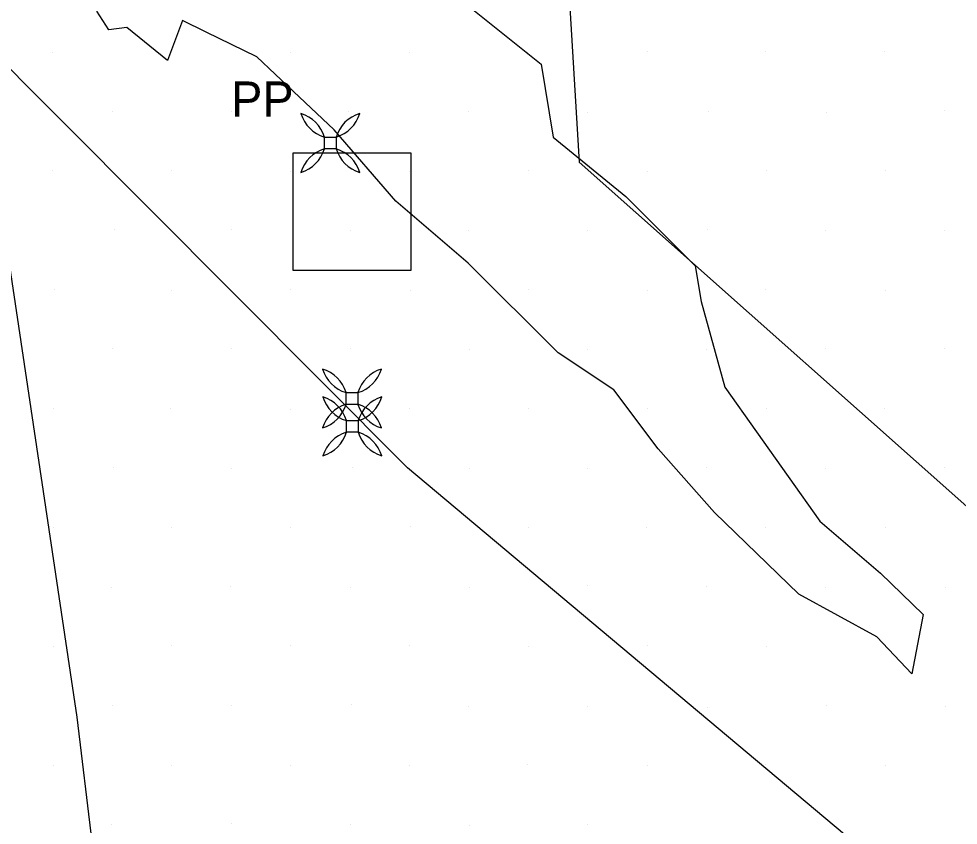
# Model space of a CAD drawing. Extents: x 1602514 to 1609837, y 863887 to 871157.
# Drawn here: x 1605707.9 to 1605875.4, y 865775.6 to 865919.5 of the extents above; entities that cross this region are included whole.
import ezdxf

# ---------------------------------------------------------------- set-up
doc = ezdxf.new("R2010")
doc.units = 0
for name, color, linetype in [('Photo-Anchor', 7, 'Continuous'), ('Survey-Entrances', 7, 'Continuous'), ('Survey-Spot dirt', 7, 'Continuous'), ('Survey-Vegetation trees', 7, 'Continuous'), ('Utility-Pole', 7, 'Continuous')]:
    doc.layers.add(name, color=color, linetype=linetype)

msp = doc.modelspace()

# ---------------------------------------------------------------- linework, layer by layer
at = {"layer": 'Photo-Anchor'}
for points in [[(1605762.4, 865898.37), (1605764.5, 865898.37), (1605764.5, 865896.27), (1605762.4, 865896.27)], [(1605762.4, 865898.37), (1605764.5, 865898.37), (1605764.5, 865896.27), (1605762.4, 865896.27)], [(1605766.26, 865852.78), (1605768.36, 865852.78), (1605768.36, 865850.68), (1605766.26, 865850.68)], [(1605766.26, 865852.78), (1605768.36, 865852.78), (1605768.36, 865850.68), (1605766.26, 865850.68)], [(1605766.33, 865847.8), (1605768.43, 865847.8), (1605768.43, 865845.7), (1605766.33, 865845.7)], [(1605766.33, 865847.8), (1605768.43, 865847.8), (1605768.43, 865845.7), (1605766.33, 865845.7)]]:
    msp.add_lwpolyline(points, close=True, dxfattribs=at)
for centre, radius, start, end in [((1605756.4, 865896.57), 6.27, 16.7236, 73.2821), ((1605764.22, 865904.39), 6.29, 196.8106, 253.1951), ((1605756.4, 865896.57), 6.27, 16.7236, 73.2821), ((1605764.22, 865904.39), 6.29, 196.8106, 253.1951), ((1605770.5, 865896.57), 6.27, 106.7179, 163.2764), ((1605762.68, 865904.39), 6.29, 286.8049, 343.1894), ((1605770.5, 865896.57), 6.27, 106.7179, 163.2764), ((1605762.68, 865904.39), 6.29, 286.8049, 343.1894), ((1605756.4, 865898.08), 6.27, 286.7179, 343.2764), ((1605764.22, 865890.25), 6.29, 106.8049, 163.1894), ((1605756.4, 865898.08), 6.27, 286.7179, 343.2764), ((1605764.22, 865890.25), 6.29, 106.8049, 163.1894), ((1605770.5, 865898.08), 6.27, 196.7236, 253.2821), ((1605762.68, 865890.25), 6.29, 16.8106, 73.1951), ((1605770.5, 865898.08), 6.27, 196.7236, 253.2821), ((1605762.68, 865890.25), 6.29, 16.8106, 73.1951), ((1605760.26, 865850.98), 6.27, 16.7236, 73.2821), ((1605768.08, 865858.8), 6.29, 196.8106, 253.1951), ((1605760.26, 865850.98), 6.27, 16.7236, 73.2821), ((1605768.08, 865858.8), 6.29, 196.8106, 253.1951), ((1605774.37, 865850.98), 6.27, 106.7179, 163.2764), ((1605766.55, 865858.8), 6.29, 286.8049, 343.1894), ((1605774.37, 865850.98), 6.27, 106.7179, 163.2764), ((1605766.55, 865858.8), 6.29, 286.8049, 343.1894), ((1605760.32, 865846), 6.27, 16.7236, 73.2821), ((1605768.14, 865853.82), 6.29, 196.8106, 253.1951), ((1605760.32, 865846), 6.27, 16.7236, 73.2821), ((1605768.14, 865853.82), 6.29, 196.8106, 253.1951), ((1605774.43, 865846), 6.27, 106.7179, 163.2764), ((1605766.61, 865853.82), 6.29, 286.8049, 343.1894), ((1605774.43, 865846), 6.27, 106.7179, 163.2764), ((1605766.61, 865853.82), 6.29, 286.8049, 343.1894), ((1605760.26, 865852.49), 6.27, 286.7179, 343.2764), ((1605768.08, 865844.67), 6.29, 106.8049, 163.1894), ((1605760.26, 865852.49), 6.27, 286.7179, 343.2764), ((1605768.08, 865844.67), 6.29, 106.8049, 163.1894), ((1605774.37, 865852.49), 6.27, 196.7236, 253.2821), ((1605766.55, 865844.67), 6.29, 16.8106, 73.1951), ((1605774.37, 865852.49), 6.27, 196.7236, 253.2821), ((1605766.55, 865844.67), 6.29, 16.8106, 73.1951), ((1605760.32, 865847.51), 6.27, 286.7179, 343.2764), ((1605768.14, 865839.68), 6.29, 106.8049, 163.1894), ((1605760.32, 865847.51), 6.27, 286.7179, 343.2764), ((1605768.14, 865839.68), 6.29, 106.8049, 163.1894), ((1605774.43, 865847.51), 6.27, 196.7236, 253.2821), ((1605766.61, 865839.68), 6.29, 16.8106, 73.1951), ((1605774.43, 865847.51), 6.27, 196.7236, 253.2821), ((1605766.61, 865839.68), 6.29, 16.8106, 73.1951)]:
    msp.add_arc(centre, radius, start, end, dxfattribs=at)
at = {"layer": 'Survey-Entrances'}
msp.add_lwpolyline([(1605786.77, 865922.81), (1605801.07, 865911.35), (1605803.18, 865898.34), (1605816.14, 865887.76), (1605828.53, 865875.41), (1605829.59, 865869.01), (1605833.8, 865853.75), (1605850.74, 865829.85), (1605861.54, 865820.59), (1605869.18, 865813.19), (1605867.15, 865802.62), (1605860.89, 865809.21), (1605847, 865816.85), (1605831.97, 865831.4), (1605821.9, 865842.78), (1605814.02, 865853.27), (1605804.11, 865859.85), (1605788.02, 865875.86), (1605775.11, 865886.92), (1605764.14, 865899.68), (1605756.91, 865906.51), (1605750.33, 865912.69), (1605741.31, 865917.08), (1605737.09, 865919.19), (1605734.41, 865912.04), (1605727.18, 865917.89), (1605723.93, 865917.48), (1605721.81, 865920.82)], dxfattribs=at)
msp.add_lwpolyline([(1605786.77, 865922.81), (1605801.07, 865911.35), (1605803.18, 865898.34), (1605816.14, 865887.76), (1605828.53, 865875.41), (1605829.59, 865869.01), (1605833.8, 865853.75), (1605850.74, 865829.85), (1605861.54, 865820.59), (1605869.18, 865813.19), (1605867.15, 865802.62), (1605860.89, 865809.21), (1605847, 865816.85), (1605831.97, 865831.4), (1605821.9, 865842.78), (1605814.02, 865853.27), (1605804.11, 865859.85), (1605788.02, 865875.86), (1605775.11, 865886.92), (1605764.14, 865899.68), (1605756.91, 865906.51), (1605750.33, 865912.69), (1605741.31, 865917.08), (1605737.09, 865919.19), (1605734.41, 865912.04), (1605727.18, 865917.89), (1605723.93, 865917.48), (1605721.81, 865920.82)], dxfattribs=at)
at = {"layer": 'Survey-Spot dirt'}
for p, q in [((1605713.87, 865913.54), (1605713.87, 865913.54)), ((1605713.87, 865913.54), (1605713.87, 865913.54)), ((1605735.13, 865913.59), (1605735.13, 865913.59)), ((1605735.13, 865913.59), (1605735.13, 865913.59)), ((1605756.43, 865913.52), (1605756.43, 865913.52)), ((1605756.43, 865913.52), (1605756.43, 865913.52)), ((1605777.6, 865913.51), (1605777.6, 865913.51)), ((1605777.6, 865913.51), (1605777.6, 865913.51)), ((1605798.64, 865913.54), (1605798.64, 865913.54)), ((1605798.64, 865913.54), (1605798.64, 865913.54)), ((1605819.94, 865913.61), (1605819.94, 865913.61)), ((1605819.94, 865913.61), (1605819.94, 865913.61)), ((1605841.09, 865913.66), (1605841.09, 865913.66)), ((1605841.09, 865913.66), (1605841.09, 865913.66)), ((1605862.35, 865913.57), (1605862.35, 865913.57)), ((1605862.35, 865913.57), (1605862.35, 865913.57)), ((1605724.63, 865902.95), (1605724.63, 865902.95)), ((1605724.63, 865902.95), (1605724.63, 865902.95)), ((1605745.76, 865902.87), (1605745.76, 865902.87)), ((1605745.76, 865902.87), (1605745.76, 865902.87)), ((1605766.77, 865902.97), (1605766.77, 865902.97)), ((1605766.77, 865902.97), (1605766.77, 865902.97)), ((1605788.1, 865902.87), (1605788.1, 865902.87)), ((1605788.1, 865902.87), (1605788.1, 865902.87)), ((1605809.38, 865902.82), (1605809.38, 865902.82)), ((1605809.38, 865902.82), (1605809.38, 865902.82)), ((1605830.8, 865903.01), (1605830.8, 865903.01)), ((1605830.8, 865903.01), (1605830.8, 865903.01)), ((1605851.85, 865902.75), (1605851.85, 865902.75)), ((1605851.85, 865902.75), (1605851.85, 865902.75)), ((1605872.98, 865903.03), (1605872.98, 865903.03)), ((1605872.98, 865903.03), (1605872.98, 865903.03)), ((1605713.96, 865892.32), (1605713.96, 865892.32)), ((1605713.96, 865892.32), (1605713.96, 865892.32)), ((1605735.15, 865892.43), (1605735.15, 865892.43)), ((1605735.15, 865892.43), (1605735.15, 865892.43)), ((1605756.35, 865892.3), (1605756.35, 865892.3)), ((1605756.35, 865892.3), (1605756.35, 865892.3)), ((1605777.64, 865892.29), (1605777.64, 865892.29)), ((1605777.64, 865892.29), (1605777.64, 865892.29)), ((1605798.72, 865892.48), (1605798.72, 865892.48)), ((1605798.72, 865892.48), (1605798.72, 865892.48)), ((1605820.05, 865892.31), (1605820.05, 865892.31)), ((1605820.05, 865892.31), (1605820.05, 865892.31)), ((1605841.18, 865892.43), (1605841.18, 865892.43)), ((1605841.18, 865892.43), (1605841.18, 865892.43)), ((1605862.45, 865892.46), (1605862.45, 865892.46)), ((1605862.45, 865892.46), (1605862.45, 865892.46)), ((1605725.04, 865881.94), (1605725.04, 865881.94)), ((1605725.04, 865881.94), (1605725.04, 865881.94)), ((1605745.8, 865881.81), (1605745.8, 865881.81)), ((1605745.8, 865881.81), (1605745.8, 865881.81)), ((1605766.97, 865881.77), (1605766.97, 865881.77)), ((1605766.97, 865881.77), (1605766.97, 865881.77)), ((1605788.18, 865881.73), (1605788.18, 865881.73)), ((1605788.18, 865881.73), (1605788.18, 865881.73)), ((1605809.34, 865881.77), (1605809.34, 865881.77)), ((1605809.34, 865881.77), (1605809.34, 865881.77)), ((1605830.64, 865881.8), (1605830.64, 865881.8)), ((1605830.64, 865881.8), (1605830.64, 865881.8)), ((1605851.74, 865881.62), (1605851.74, 865881.62)), ((1605851.74, 865881.62), (1605851.74, 865881.62)), ((1605873.01, 865881.7), (1605873.01, 865881.7)), ((1605873.01, 865881.7), (1605873.01, 865881.7)), ((1605714.25, 865871.2), (1605714.25, 865871.2)), ((1605714.25, 865871.2), (1605714.25, 865871.2)), ((1605735.14, 865870.95), (1605735.14, 865870.95)), ((1605735.14, 865870.95), (1605735.14, 865870.95)), ((1605756.36, 865871.12), (1605756.36, 865871.12)), ((1605756.36, 865871.12), (1605756.36, 865871.12)), ((1605777.67, 865871.03), (1605777.67, 865871.03)), ((1605777.67, 865871.03), (1605777.67, 865871.03)), ((1605798.84, 865871.11), (1605798.84, 865871.11)), ((1605798.84, 865871.11), (1605798.84, 865871.11)), ((1605819.93, 865870.98), (1605819.93, 865870.98)), ((1605819.93, 865870.98), (1605819.93, 865870.98)), ((1605841.11, 865871.19), (1605841.11, 865871.19)), ((1605841.11, 865871.19), (1605841.11, 865871.19)), ((1605862.44, 865871.07), (1605862.44, 865871.07)), ((1605862.44, 865871.07), (1605862.44, 865871.07)), ((1605724.68, 865860.63), (1605724.68, 865860.63)), ((1605724.68, 865860.63), (1605724.68, 865860.63)), ((1605745.75, 865860.64), (1605745.75, 865860.64)), ((1605745.75, 865860.64), (1605745.75, 865860.64)), ((1605767.01, 865860.66), (1605767.01, 865860.66)), ((1605767.01, 865860.66), (1605767.01, 865860.66)), ((1605788.21, 865860.45), (1605788.21, 865860.45)), ((1605788.21, 865860.45), (1605788.21, 865860.45)), ((1605809.39, 865860.54), (1605809.39, 865860.54)), ((1605809.39, 865860.54), (1605809.39, 865860.54)), ((1605830.62, 865860.47), (1605830.62, 865860.47)), ((1605830.62, 865860.47), (1605830.62, 865860.47)), ((1605851.83, 865860.59), (1605851.83, 865860.59)), ((1605851.83, 865860.59), (1605851.83, 865860.59)), ((1605873.06, 865860.61), (1605873.06, 865860.61)), ((1605873.06, 865860.61), (1605873.06, 865860.61)), ((1605714.01, 865849.92), (1605714.01, 865849.92)), ((1605714.01, 865849.92), (1605714.01, 865849.92)), ((1605734.99, 865849.94), (1605734.99, 865849.94)), ((1605734.99, 865849.94), (1605734.99, 865849.94)), ((1605756.38, 865849.68), (1605756.38, 865849.68)), ((1605756.38, 865849.68), (1605756.38, 865849.68)), ((1605777.59, 865849.92), (1605777.59, 865849.92)), ((1605777.59, 865849.92), (1605777.59, 865849.92)), ((1605798.79, 865849.96), (1605798.79, 865849.96)), ((1605798.79, 865849.96), (1605798.79, 865849.96)), ((1605820.01, 865850), (1605820.01, 865850)), ((1605820.01, 865850), (1605820.01, 865850)), ((1605841.27, 865849.92), (1605841.27, 865849.92)), ((1605841.27, 865849.92), (1605841.27, 865849.92)), ((1605862.3, 865849.97), (1605862.3, 865849.97)), ((1605862.3, 865849.97), (1605862.3, 865849.97)), ((1605724.82, 865839.45), (1605724.82, 865839.45)), ((1605724.82, 865839.45), (1605724.82, 865839.45)), ((1605745.76, 865839.28), (1605745.76, 865839.28)), ((1605745.76, 865839.28), (1605745.76, 865839.28)), ((1605767.47, 865839.34), (1605767.47, 865839.34)), ((1605767.47, 865839.34), (1605767.47, 865839.34)), ((1605788.2, 865839.25), (1605788.2, 865839.25)), ((1605788.2, 865839.25), (1605788.2, 865839.25)), ((1605809.37, 865839.3), (1605809.37, 865839.3)), ((1605809.37, 865839.3), (1605809.37, 865839.3)), ((1605830.53, 865839.36), (1605830.53, 865839.36)), ((1605830.53, 865839.36), (1605830.53, 865839.36)), ((1605851.82, 865839.26), (1605851.82, 865839.26)), ((1605851.82, 865839.26), (1605851.82, 865839.26)), ((1605872.99, 865839.41), (1605872.99, 865839.41)), ((1605872.99, 865839.41), (1605872.99, 865839.41)), ((1605714.02, 865828.66), (1605714.02, 865828.66)), ((1605714.02, 865828.66), (1605714.02, 865828.66)), ((1605735.06, 865828.76), (1605735.06, 865828.76)), ((1605735.06, 865828.76), (1605735.06, 865828.76)), ((1605756.41, 865828.71), (1605756.41, 865828.71)), ((1605756.41, 865828.71), (1605756.41, 865828.71)), ((1605777.73, 865828.86), (1605777.73, 865828.86)), ((1605777.73, 865828.86), (1605777.73, 865828.86)), ((1605798.8, 865828.79), (1605798.8, 865828.79)), ((1605798.8, 865828.79), (1605798.8, 865828.79)), ((1605819.9, 865828.68), (1605819.9, 865828.68)), ((1605819.9, 865828.68), (1605819.9, 865828.68)), ((1605841.14, 865828.73), (1605841.14, 865828.73)), ((1605841.14, 865828.73), (1605841.14, 865828.73)), ((1605862.46, 865828.77), (1605862.46, 865828.77)), ((1605862.46, 865828.77), (1605862.46, 865828.77)), ((1605809.37, 865818.3), (1605809.37, 865818.3)), ((1605809.37, 865818.3), (1605809.37, 865818.3)), ((1605724.44, 865817.96), (1605724.44, 865817.96)), ((1605724.44, 865817.96), (1605724.44, 865817.96)), ((1605745.66, 865818.25), (1605745.66, 865818.25)), ((1605745.66, 865818.25), (1605745.66, 865818.25)), ((1605767.06, 865817.98), (1605767.06, 865817.98)), ((1605767.06, 865817.98), (1605767.06, 865817.98)), ((1605788.2, 865818.03), (1605788.2, 865818.03)), ((1605788.2, 865818.03), (1605788.2, 865818.03)), ((1605830.56, 865818.14), (1605830.56, 865818.14)), ((1605830.56, 865818.14), (1605830.56, 865818.14)), ((1605851.8, 865818.1), (1605851.8, 865818.1)), ((1605851.8, 865818.1), (1605851.8, 865818.1)), ((1605873.08, 865818.03), (1605873.08, 865818.03)), ((1605873.08, 865818.03), (1605873.08, 865818.03)), ((1605714, 865807.42), (1605714, 865807.42)), ((1605714, 865807.42), (1605714, 865807.42)), ((1605735.2, 865807.61), (1605735.2, 865807.61)), ((1605735.2, 865807.61), (1605735.2, 865807.61)), ((1605756.29, 865807.58), (1605756.29, 865807.58)), ((1605756.29, 865807.58), (1605756.29, 865807.58)), ((1605777.5, 865807.61), (1605777.5, 865807.61)), ((1605777.5, 865807.61), (1605777.5, 865807.61)), ((1605798.8, 865807.57), (1605798.8, 865807.57)), ((1605798.8, 865807.57), (1605798.8, 865807.57)), ((1605819.96, 865807.67), (1605819.96, 865807.67)), ((1605819.96, 865807.67), (1605819.96, 865807.67)), ((1605841.29, 865807.53), (1605841.29, 865807.53)), ((1605841.29, 865807.53), (1605841.29, 865807.53)), ((1605862.48, 865807.54), (1605862.48, 865807.54)), ((1605862.48, 865807.54), (1605862.48, 865807.54)), ((1605724.53, 865796.96), (1605724.53, 865796.96)), ((1605724.53, 865796.96), (1605724.53, 865796.96)), ((1605745.78, 865796.93), (1605745.78, 865796.93)), ((1605745.78, 865796.93), (1605745.78, 865796.93)), ((1605767.14, 865797.07), (1605767.14, 865797.07)), ((1605767.14, 865797.07), (1605767.14, 865797.07)), ((1605788.16, 865796.87), (1605788.16, 865796.87)), ((1605788.16, 865796.87), (1605788.16, 865796.87)), ((1605809.34, 865796.7), (1605809.34, 865796.7)), ((1605809.34, 865796.7), (1605809.34, 865796.7)), ((1605830.7, 865796.66), (1605830.7, 865796.66)), ((1605830.7, 865796.66), (1605830.7, 865796.66)), ((1605851.89, 865796.95), (1605851.89, 865796.95)), ((1605851.89, 865796.95), (1605851.89, 865796.95)), ((1605873.09, 865796.86), (1605873.09, 865796.86)), ((1605873.09, 865796.86), (1605873.09, 865796.86)), ((1605841.02, 865786.45), (1605841.02, 865786.45)), ((1605841.02, 865786.45), (1605841.02, 865786.45)), ((1605714, 865786.3), (1605714, 865786.3)), ((1605714, 865786.3), (1605714, 865786.3)), ((1605735.11, 865786.29), (1605735.11, 865786.29)), ((1605735.11, 865786.29), (1605735.11, 865786.29)), ((1605756.34, 865786.26), (1605756.34, 865786.26)), ((1605756.34, 865786.26), (1605756.34, 865786.26)), ((1605777.62, 865786.26), (1605777.62, 865786.26)), ((1605777.62, 865786.26), (1605777.62, 865786.26)), ((1605798.66, 865786.35), (1605798.66, 865786.35)), ((1605798.66, 865786.35), (1605798.66, 865786.35)), ((1605819.96, 865786.31), (1605819.96, 865786.31)), ((1605819.96, 865786.31), (1605819.96, 865786.31)), ((1605862.44, 865786.32), (1605862.44, 865786.32)), ((1605862.44, 865786.32), (1605862.44, 865786.32)), ((1605724.49, 865775.7), (1605724.49, 865775.7)), ((1605724.49, 865775.7), (1605724.49, 865775.7)), ((1605745.75, 865775.84), (1605745.75, 865775.84)), ((1605745.75, 865775.84), (1605745.75, 865775.84)), ((1605766.98, 865775.71), (1605766.98, 865775.71)), ((1605766.98, 865775.71), (1605766.98, 865775.71)), ((1605788.23, 865775.6), (1605788.23, 865775.6)), ((1605788.23, 865775.6), (1605788.23, 865775.6)), ((1605809.38, 865775.66), (1605809.38, 865775.66)), ((1605809.38, 865775.66), (1605809.38, 865775.66))]:
    msp.add_line(p, q, dxfattribs=at)
at = {"layer": 'Survey-Vegetation trees'}
for points in [[(1605665.45, 866233.32), (1605801.74, 865994.52), (1605807.84, 865893.89), (1606209.37, 865537.1), (1606668.8, 865151.33), (1606667.28, 865042.31)], [(1605665.45, 866233.32), (1605801.74, 865994.52), (1605807.84, 865893.89), (1606209.37, 865537.1), (1606668.8, 865151.33), (1606667.28, 865042.31)], [(1606615.31, 865062.49), (1606607.69, 865114.33), (1606446.16, 865257.66), (1606056.06, 865605.3), (1605777.2, 865839.35), (1605699.98, 865916.85), (1605718.27, 865794.87), (1605734.27, 865661.45), (1605756.36, 865515.84)], [(1606615.31, 865062.49), (1606607.69, 865114.33), (1606446.16, 865257.66), (1606056.06, 865605.3), (1605777.2, 865839.35), (1605699.98, 865916.85), (1605718.27, 865794.87), (1605734.27, 865661.45), (1605756.36, 865515.84)]]:
    msp.add_lwpolyline(points, dxfattribs=at)
at = {"layer": 'Utility-Pole'}
msp.add_lwpolyline([(1605756.81, 865895.57), (1605777.82, 865895.57), (1605777.82, 865874.56), (1605756.81, 865874.56)], close=True, dxfattribs=at)
msp.add_lwpolyline([(1605756.81, 865895.57), (1605777.82, 865895.57), (1605777.82, 865874.56), (1605756.81, 865874.56)], close=True, dxfattribs=at)

# ---------------------------------------------------------------- texts
msp.add_text('PP', height=6.251, dxfattribs=at).set_placement((1605745.76, 865902.04))
msp.add_text('PP', height=6.251, dxfattribs=at).set_placement((1605745.76, 865902.04))

doc.saveas('drawing.dxf')
